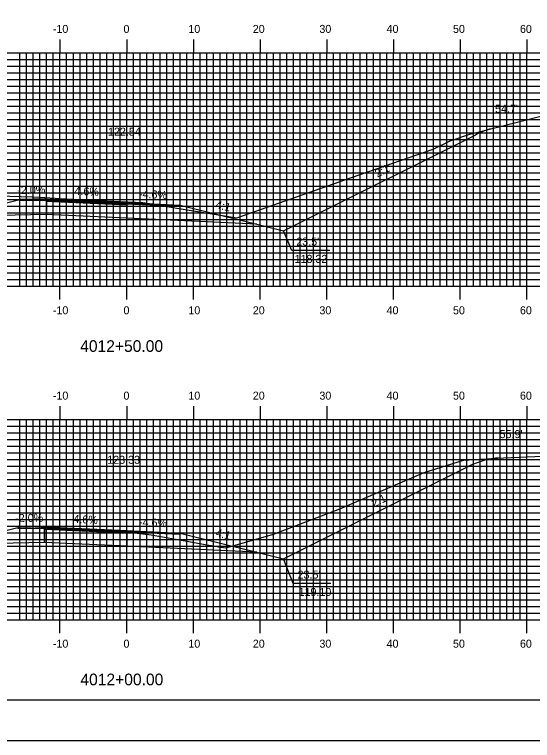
# Model space of a CAD drawing. Extents: x 852934 to 853277, y 364661 to 364881.
# Drawn here: x 853083 to 853160.6, y 364661.3 to 364770.1 of the extents above; entities that cross this region are included whole.
import ezdxf

# ---------------------------------------------------------------- set-up
doc = ezdxf.new("R2010")
doc.units = 0
for name, color, linetype in [('ANNOTATION', 7, 'Continuous'), ('BORDER', 7, 'Continuous'), ('D_Roadway_Centerline_Text', 7, 'Continuous'), ('D_Roadway_Edge_Shoulder', 7, 'Continuous'), ('D_Roadway_Edge_TW', 7, 'Continuous'), ('D_Roadway_Pavement', 7, 'Continuous'), ('D_Roadway_SlopeLines', 7, 'Continuous'), ('D_Roadway_SubGrade', 7, 'Continuous'), ('D_Text_Standard', 7, 'Continuous'), ('H_V ANNOTATION', 7, 'Continuous'), ('M_Roadway_Centerline', 7, 'Continuous'), ('MAJOR', 7, 'Continuous'), ('MINOR', 7, 'Continuous'), ('PLOT BOUNDARY', 7, 'Continuous'), ('S_Roadway_Centerline', 7, 'Continuous')]:
    doc.layers.add(name, color=color, linetype=linetype)

msp = doc.modelspace()

# ---------------------------------------------------------------- linework, layer by layer
at = {"layer": 'ANNOTATION'}
for points in [[(853119.29, 364738.69), (853123.29, 364737.69), (853125.29, 364738.69), (853152.12, 364752.1)], [(853130.22, 364734.75), (853124.53, 364734.75), (853123.29, 364737.69)], [(853119.29, 364689.47), (853123.29, 364688.47), (853125.29, 364689.47), (853151.1, 364702.38)], [(853130.41, 364684.8), (853124.72, 364684.8), (853123.29, 364688.47)]]:
    msp.add_lwpolyline(points, dxfattribs=at)
at = {"layer": 'BORDER'}
msp.add_lwpolyline([(852950.18, 364667.37), (853270.18, 364667.37), (853270.18, 364877.37), (852950.18, 364877.37)], close=True, dxfattribs=at)
at = {"layer": 'D_Roadway_Edge_Shoulder'}
for points in [[(853087.78, 364742.48), (853083.78, 364742.4), (853083.78, 364742.24), (853087.78, 364742.3)], [(853099.78, 364741.93), (853107.78, 364741.56), (853107.78, 364741.4), (853099.78, 364741.75)], [(853087.47, 364693.28), (853083.47, 364693.2), (853083.47, 364693.03), (853087.47, 364693.1)], [(853099.78, 364692.72), (853107.78, 364692.35), (853107.78, 364692.18), (853099.78, 364692.53)]]:
    msp.add_lwpolyline(points, close=True, dxfattribs=at)
at = {"layer": 'D_Roadway_Edge_TW'}
for points in [[(853087.78, 364742.48), (853099.78, 364741.93), (853099.78, 364741.75), (853087.78, 364742.3)], [(853087.47, 364693.28), (853099.78, 364692.72), (853099.78, 364692.53), (853087.47, 364693.1)]]:
    msp.add_lwpolyline(points, close=True, dxfattribs=at)
at = {"layer": 'D_Roadway_Pavement'}
for points in [[(853087.78, 364742.3), (853099.78, 364741.75), (853099.78, 364741.58), (853087.78, 364742.14)], [(853087.47, 364693.1), (853099.78, 364692.53), (853099.78, 364692.37), (853087.47, 364692.93)]]:
    msp.add_lwpolyline(points, close=True, dxfattribs=at)
for points in [[(853087.78, 364742.3), (853087.78, 364742.14)], [(853099.78, 364741.75), (853099.78, 364741.58)], [(853099.78, 364741.75), (853099.78, 364741.58)], [(853087.47, 364693.1), (853087.47, 364692.93)], [(853099.78, 364692.53), (853099.78, 364692.37)], [(853099.78, 364692.53), (853099.78, 364692.37)]]:
    msp.add_lwpolyline(points, dxfattribs=at)
at = {"layer": 'D_Roadway_SlopeLines'}
for centre, start in [((853157.48, 364741.37), 104.298), ((853156.47, 364691.65), 93.6927)]:
    msp.add_arc(centre, 12, start, 116.5651, dxfattribs=at)
at = {"layer": 'D_Roadway_SubGrade'}
for points in [[(853087.78, 364740.14), (853073.57, 364739.85), (853083.78, 364742.4), (853083.78, 364742.24), (853087.78, 364742.3), (853087.78, 364742.14)], [(853087.78, 364742.14), (853099.78, 364741.58), (853099.78, 364739.58), (853087.78, 364740.14)], [(853099.78, 364741.58), (853099.78, 364741.75), (853107.78, 364741.4), (853107.78, 364741.56), (853119.29, 364738.69), (853099.78, 364739.58)], [(853087.47, 364690.93), (853073.26, 364690.65), (853083.47, 364693.2), (853083.47, 364693.03), (853087.47, 364693.1), (853087.47, 364692.93)], [(853087.47, 364692.93), (853099.78, 364692.37), (853099.78, 364690.37), (853087.47, 364690.93)], [(853099.78, 364692.37), (853099.78, 364692.53), (853107.78, 364692.18), (853107.78, 364692.35), (853119.3, 364689.47), (853099.78, 364690.37)]]:
    msp.add_lwpolyline(points, close=True, dxfattribs=at)
at = {"layer": 'MAJOR'}
for p, q in [((853089.78, 364766.37), (853089.78, 364764.37)), ((853099.78, 364766.37), (853099.78, 364764.37)), ((853109.78, 364766.37), (853109.78, 364764.37)), ((853119.78, 364766.37), (853119.78, 364764.37)), ((853129.78, 364766.37), (853129.78, 364764.37)), ((853139.78, 364766.37), (853139.78, 364764.37)), ((853149.78, 364766.37), (853149.78, 364764.37)), ((853159.78, 364766.37), (853159.78, 364764.37)), ((852959.78, 364764.37), (853239.78, 364764.37)), ((852959.78, 364764.37), (853239.78, 364764.37)), ((853089.78, 364729.37), (853089.78, 364764.37)), ((853099.78, 364729.37), (853099.78, 364764.37)), ((853109.78, 364729.37), (853109.78, 364764.37)), ((853119.78, 364729.37), (853119.78, 364764.37)), ((853129.78, 364729.37), (853129.78, 364764.37)), ((853139.78, 364729.37), (853139.78, 364764.37)), ((853149.78, 364729.37), (853149.78, 364764.37)), ((853159.78, 364729.37), (853159.78, 364764.37)), ((852959.78, 364759.37), (853239.78, 364759.37)), ((852959.78, 364754.37), (853239.78, 364754.37)), ((852959.78, 364749.37), (853239.78, 364749.37)), ((852959.78, 364744.37), (853239.78, 364744.37)), ((852959.78, 364739.37), (853239.78, 364739.37)), ((852959.78, 364734.37), (853239.78, 364734.37)), ((852959.78, 364729.37), (853239.78, 364729.37)), ((852959.78, 364729.37), (853239.78, 364729.37)), ((853089.78, 364727.37), (853089.78, 364729.37)), ((853099.78, 364727.37), (853099.78, 364729.37)), ((853109.78, 364727.37), (853109.78, 364729.37)), ((853119.78, 364727.37), (853119.78, 364729.37)), ((853129.78, 364727.37), (853129.78, 364729.37)), ((853139.78, 364727.37), (853139.78, 364729.37)), ((853149.78, 364727.37), (853149.78, 364729.37)), ((853159.78, 364727.37), (853159.78, 364729.37)), ((853089.78, 364711.37), (853089.78, 364709.37)), ((853099.78, 364711.37), (853099.78, 364709.37)), ((853109.78, 364711.37), (853109.78, 364709.37)), ((853119.78, 364711.37), (853119.78, 364709.37)), ((853129.78, 364711.37), (853129.78, 364709.37)), ((853139.78, 364711.37), (853139.78, 364709.37)), ((853149.78, 364711.37), (853149.78, 364709.37)), ((853159.78, 364711.37), (853159.78, 364709.37)), ((852959.78, 364709.37), (853239.78, 364709.37)), ((852959.78, 364709.37), (853239.78, 364709.37)), ((853089.78, 364679.37), (853089.78, 364709.37)), ((853099.78, 364679.37), (853099.78, 364709.37)), ((853109.78, 364679.37), (853109.78, 364709.37)), ((853119.78, 364679.37), (853119.78, 364709.37)), ((853129.78, 364679.37), (853129.78, 364709.37)), ((853139.78, 364679.37), (853139.78, 364709.37)), ((853149.78, 364679.37), (853149.78, 364709.37)), ((853159.78, 364679.37), (853159.78, 364709.37)), ((852959.78, 364704.37), (853239.78, 364704.37)), ((852959.78, 364699.37), (853239.78, 364699.37)), ((852959.78, 364694.37), (853239.78, 364694.37)), ((852959.78, 364689.37), (853239.78, 364689.37)), ((852959.78, 364684.37), (853239.78, 364684.37)), ((852959.78, 364679.37), (853239.78, 364679.37)), ((852959.78, 364679.37), (853239.78, 364679.37)), ((853089.78, 364677.37), (853089.78, 364679.37)), ((853099.78, 364677.37), (853099.78, 364679.37)), ((853109.78, 364677.37), (853109.78, 364679.37)), ((853119.78, 364677.37), (853119.78, 364679.37)), ((853129.78, 364677.37), (853129.78, 364679.37)), ((853139.78, 364677.37), (853139.78, 364679.37)), ((853149.78, 364677.37), (853149.78, 364679.37)), ((853159.78, 364677.37), (853159.78, 364679.37))]:
    msp.add_line(p, q, dxfattribs=at)
at = {"layer": 'MINOR'}
for p, q in [((853083.78, 364729.37), (853083.78, 364764.37)), ((853084.78, 364729.37), (853084.78, 364764.37)), ((853085.78, 364729.37), (853085.78, 364764.37)), ((853086.78, 364729.37), (853086.78, 364764.37)), ((853087.78, 364729.37), (853087.78, 364764.37)), ((853088.78, 364729.37), (853088.78, 364764.37)), ((853090.78, 364729.37), (853090.78, 364764.37)), ((853091.78, 364729.37), (853091.78, 364764.37)), ((853092.78, 364729.37), (853092.78, 364764.37)), ((853093.78, 364729.37), (853093.78, 364764.37)), ((853094.78, 364729.37), (853094.78, 364764.37)), ((853095.78, 364729.37), (853095.78, 364764.37)), ((853096.78, 364729.37), (853096.78, 364764.37)), ((853097.78, 364729.37), (853097.78, 364764.37)), ((853098.78, 364729.37), (853098.78, 364764.37)), ((853100.78, 364729.37), (853100.78, 364764.37)), ((853101.78, 364729.37), (853101.78, 364764.37)), ((853102.78, 364729.37), (853102.78, 364764.37)), ((853103.78, 364729.37), (853103.78, 364764.37)), ((853104.78, 364729.37), (853104.78, 364764.37)), ((853105.78, 364729.37), (853105.78, 364764.37)), ((853106.78, 364729.37), (853106.78, 364764.37)), ((853107.78, 364729.37), (853107.78, 364764.37)), ((853108.78, 364729.37), (853108.78, 364764.37)), ((853110.78, 364729.37), (853110.78, 364764.37)), ((853111.78, 364729.37), (853111.78, 364764.37)), ((853112.78, 364729.37), (853112.78, 364764.37)), ((853113.78, 364729.37), (853113.78, 364764.37)), ((853114.78, 364729.37), (853114.78, 364764.37)), ((853115.78, 364729.37), (853115.78, 364764.37)), ((853116.78, 364729.37), (853116.78, 364764.37)), ((853117.78, 364729.37), (853117.78, 364764.37)), ((853118.78, 364729.37), (853118.78, 364764.37)), ((853120.78, 364729.37), (853120.78, 364764.37)), ((853121.78, 364729.37), (853121.78, 364764.37)), ((853122.78, 364729.37), (853122.78, 364764.37)), ((853123.78, 364729.37), (853123.78, 364764.37)), ((853124.78, 364729.37), (853124.78, 364764.37)), ((853125.78, 364729.37), (853125.78, 364764.37)), ((853126.78, 364729.37), (853126.78, 364764.37)), ((853127.78, 364729.37), (853127.78, 364764.37)), ((853128.78, 364729.37), (853128.78, 364764.37)), ((853130.78, 364729.37), (853130.78, 364764.37)), ((853131.78, 364729.37), (853131.78, 364764.37)), ((853132.78, 364729.37), (853132.78, 364764.37)), ((853133.78, 364729.37), (853133.78, 364764.37)), ((853134.78, 364729.37), (853134.78, 364764.37)), ((853135.78, 364729.37), (853135.78, 364764.37)), ((853136.78, 364729.37), (853136.78, 364764.37)), ((853137.78, 364729.37), (853137.78, 364764.37)), ((853138.78, 364729.37), (853138.78, 364764.37)), ((853140.78, 364729.37), (853140.78, 364764.37)), ((853141.78, 364729.37), (853141.78, 364764.37)), ((853142.78, 364729.37), (853142.78, 364764.37)), ((853143.78, 364729.37), (853143.78, 364764.37)), ((853144.78, 364729.37), (853144.78, 364764.37)), ((853145.78, 364729.37), (853145.78, 364764.37)), ((853146.78, 364729.37), (853146.78, 364764.37)), ((853147.78, 364729.37), (853147.78, 364764.37)), ((853148.78, 364729.37), (853148.78, 364764.37)), ((853150.78, 364729.37), (853150.78, 364764.37)), ((853151.78, 364729.37), (853151.78, 364764.37)), ((853152.78, 364729.37), (853152.78, 364764.37)), ((853153.78, 364729.37), (853153.78, 364764.37)), ((853154.78, 364729.37), (853154.78, 364764.37)), ((853155.78, 364729.37), (853155.78, 364764.37)), ((853156.78, 364729.37), (853156.78, 364764.37)), ((853157.78, 364729.37), (853157.78, 364764.37)), ((853158.78, 364729.37), (853158.78, 364764.37)), ((852959.78, 364763.37), (853239.78, 364763.37)), ((852959.78, 364762.37), (853239.78, 364762.37)), ((852959.78, 364761.37), (853239.78, 364761.37)), ((852959.78, 364760.37), (853239.78, 364760.37)), ((852959.78, 364758.37), (853239.78, 364758.37)), ((852959.78, 364757.37), (853239.78, 364757.37)), ((852959.78, 364756.37), (853239.78, 364756.37)), ((852959.78, 364755.37), (853239.78, 364755.37)), ((852959.78, 364753.37), (853239.78, 364753.37)), ((852959.78, 364752.37), (853239.78, 364752.37)), ((852959.78, 364751.37), (853239.78, 364751.37)), ((852959.78, 364750.37), (853239.78, 364750.37)), ((852959.78, 364748.37), (853239.78, 364748.37)), ((852959.78, 364747.37), (853239.78, 364747.37)), ((852959.78, 364746.37), (853239.78, 364746.37)), ((852959.78, 364745.37), (853239.78, 364745.37)), ((852959.78, 364743.37), (853239.78, 364743.37)), ((852959.78, 364742.37), (853239.78, 364742.37)), ((852959.78, 364741.37), (853239.78, 364741.37)), ((852959.78, 364740.37), (853239.78, 364740.37)), ((852959.78, 364738.37), (853239.78, 364738.37)), ((852959.78, 364737.37), (853239.78, 364737.37)), ((852959.78, 364736.37), (853239.78, 364736.37)), ((852959.78, 364735.37), (853239.78, 364735.37)), ((852959.78, 364733.37), (853239.78, 364733.37)), ((852959.78, 364732.37), (853239.78, 364732.37)), ((852959.78, 364731.37), (853239.78, 364731.37)), ((852959.78, 364730.37), (853239.78, 364730.37)), ((853083.78, 364679.37), (853083.78, 364709.37)), ((853084.78, 364679.37), (853084.78, 364709.37)), ((853085.78, 364679.37), (853085.78, 364709.37)), ((853086.78, 364679.37), (853086.78, 364709.37)), ((853087.78, 364679.37), (853087.78, 364709.37)), ((853088.78, 364679.37), (853088.78, 364709.37)), ((853090.78, 364679.37), (853090.78, 364709.37)), ((853091.78, 364679.37), (853091.78, 364709.37)), ((853092.78, 364679.37), (853092.78, 364709.37)), ((853093.78, 364679.37), (853093.78, 364709.37)), ((853094.78, 364679.37), (853094.78, 364709.37)), ((853095.78, 364679.37), (853095.78, 364709.37)), ((853096.78, 364679.37), (853096.78, 364709.37)), ((853097.78, 364679.37), (853097.78, 364709.37)), ((853098.78, 364679.37), (853098.78, 364709.37)), ((853100.78, 364679.37), (853100.78, 364709.37)), ((853101.78, 364679.37), (853101.78, 364709.37)), ((853102.78, 364679.37), (853102.78, 364709.37)), ((853103.78, 364679.37), (853103.78, 364709.37)), ((853104.78, 364679.37), (853104.78, 364709.37)), ((853105.78, 364679.37), (853105.78, 364709.37)), ((853106.78, 364679.37), (853106.78, 364709.37)), ((853107.78, 364679.37), (853107.78, 364709.37)), ((853108.78, 364679.37), (853108.78, 364709.37)), ((853110.78, 364679.37), (853110.78, 364709.37)), ((853111.78, 364679.37), (853111.78, 364709.37)), ((853112.78, 364679.37), (853112.78, 364709.37)), ((853113.78, 364679.37), (853113.78, 364709.37)), ((853114.78, 364679.37), (853114.78, 364709.37)), ((853115.78, 364679.37), (853115.78, 364709.37)), ((853116.78, 364679.37), (853116.78, 364709.37)), ((853117.78, 364679.37), (853117.78, 364709.37)), ((853118.78, 364679.37), (853118.78, 364709.37)), ((853120.78, 364679.37), (853120.78, 364709.37)), ((853121.78, 364679.37), (853121.78, 364709.37)), ((853122.78, 364679.37), (853122.78, 364709.37)), ((853123.78, 364679.37), (853123.78, 364709.37)), ((853124.78, 364679.37), (853124.78, 364709.37)), ((853125.78, 364679.37), (853125.78, 364709.37)), ((853126.78, 364679.37), (853126.78, 364709.37)), ((853127.78, 364679.37), (853127.78, 364709.37)), ((853128.78, 364679.37), (853128.78, 364709.37)), ((853130.78, 364679.37), (853130.78, 364709.37)), ((853131.78, 364679.37), (853131.78, 364709.37)), ((853132.78, 364679.37), (853132.78, 364709.37)), ((853133.78, 364679.37), (853133.78, 364709.37)), ((853134.78, 364679.37), (853134.78, 364709.37)), ((853135.78, 364679.37), (853135.78, 364709.37)), ((853136.78, 364679.37), (853136.78, 364709.37)), ((853137.78, 364679.37), (853137.78, 364709.37)), ((853138.78, 364679.37), (853138.78, 364709.37)), ((853140.78, 364679.37), (853140.78, 364709.37)), ((853141.78, 364679.37), (853141.78, 364709.37)), ((853142.78, 364679.37), (853142.78, 364709.37)), ((853143.78, 364679.37), (853143.78, 364709.37)), ((853144.78, 364679.37), (853144.78, 364709.37)), ((853145.78, 364679.37), (853145.78, 364709.37)), ((853146.78, 364679.37), (853146.78, 364709.37)), ((853147.78, 364679.37), (853147.78, 364709.37)), ((853148.78, 364679.37), (853148.78, 364709.37)), ((853150.78, 364679.37), (853150.78, 364709.37)), ((853151.78, 364679.37), (853151.78, 364709.37)), ((853152.78, 364679.37), (853152.78, 364709.37)), ((853153.78, 364679.37), (853153.78, 364709.37)), ((853154.78, 364679.37), (853154.78, 364709.37)), ((853155.78, 364679.37), (853155.78, 364709.37)), ((853156.78, 364679.37), (853156.78, 364709.37)), ((853157.78, 364679.37), (853157.78, 364709.37)), ((853158.78, 364679.37), (853158.78, 364709.37)), ((852959.78, 364708.37), (853239.78, 364708.37)), ((852959.78, 364707.37), (853239.78, 364707.37)), ((852959.78, 364706.37), (853239.78, 364706.37)), ((852959.78, 364705.37), (853239.78, 364705.37)), ((852959.78, 364703.37), (853239.78, 364703.37)), ((852959.78, 364702.37), (853239.78, 364702.37)), ((852959.78, 364701.37), (853239.78, 364701.37)), ((852959.78, 364700.37), (853239.78, 364700.37)), ((852959.78, 364698.37), (853239.78, 364698.37)), ((852959.78, 364697.37), (853239.78, 364697.37)), ((852959.78, 364696.37), (853239.78, 364696.37)), ((852959.78, 364695.37), (853239.78, 364695.37)), ((852959.78, 364693.37), (853239.78, 364693.37)), ((852959.78, 364692.37), (853239.78, 364692.37)), ((852959.78, 364691.37), (853239.78, 364691.37)), ((852959.78, 364690.37), (853239.78, 364690.37)), ((852959.78, 364688.37), (853239.78, 364688.37)), ((852959.78, 364687.37), (853239.78, 364687.37)), ((852959.78, 364686.37), (853239.78, 364686.37)), ((852959.78, 364685.37), (853239.78, 364685.37)), ((852959.78, 364683.37), (853239.78, 364683.37)), ((852959.78, 364682.37), (853239.78, 364682.37)), ((852959.78, 364681.37), (853239.78, 364681.37)), ((852959.78, 364680.37), (853239.78, 364680.37))]:
    msp.add_line(p, q, dxfattribs=at)
at = {"layer": 'PLOT BOUNDARY'}
msp.add_lwpolyline([(852933.99, 364661.25), (853273.99, 364661.25), (853273.99, 364881.25), (852933.99, 364881.25)], close=True, dxfattribs=at)
at = {"layer": 'S_Roadway_Centerline'}
for points in [[(853080.57, 364742.96), (853085.62, 364742.77), (853086.76, 364742.73), (853089.81, 364742.54), (853097.74, 364742.13), (853102.21, 364741.92), (853103.53, 364741.73), (853104.77, 364741.56), (853107.02, 364741.14), (853116.31, 364739.63), (853133.5, 364745.67), (853145.72, 364749.95), (853148.29, 364751.17), (853151.22, 364752.16), (853169.96, 364756.93)], [(853081.71, 364693.46), (853083.32, 364693.41), (853083.53, 364693.43), (853090.34, 364693.04), (853096.21, 364692.73), (853098.81, 364692.62), (853103.43, 364692.07), (853109.08, 364691.1), (853111.55, 364690.66), (853113.12, 364690.37), (853113.54, 364690.31), (853114.66, 364690.15), (853121.78, 364692.2), (853131.76, 364695.99), (853144.38, 364701.46), (853150.3, 364703.27), (853156.26, 364703.66), (853169.25, 364704.21)]]:
    msp.add_lwpolyline(points, dxfattribs=at)

# ---------------------------------------------------------------- texts
at = {"layer": 'ANNOTATION'}
for s, rotation, p in [('2:1', 26.5651, (853137.37, 364745.66)), ('-2.0%', 1.1458, (853083.39, 364743.2)), ('4.6%', 357.3663, (853091.93, 364743.1)), ('-4.6%', 357.3663, (853101.61, 364742.65)), ('4:1', 345.9638, (853113.04, 364741.11)), ('2:1', 26.5651, (853136.86, 364696.19)), ('-2.0%', 1.1458, (853083.08, 364693.99)), ('4.6%', 357.3663, (853091.77, 364693.89)), ('-4.6%', 357.3663, (853101.61, 364693.43)), ('4:1', 345.9638, (853113.05, 364691.89))]:
    msp.add_text(s, height=1.2, rotation=rotation, dxfattribs=at).set_placement(p)
for s, p in [("23.5' ", (853125.22, 364735.48)), ('118.32', (853124.96, 364732.88)), ("23.5' ", (853125.41, 364685.53)), ('119.10', (853125.56, 364682.93))]:
    msp.add_text(s, height=1.2, dxfattribs=at).set_placement(p)
at = {"layer": 'D_Roadway_Centerline_Text'}
for s, p in [('122.54', (853096.98, 364751.96)), ('123.33', (853096.87, 364702.75))]:
    msp.add_text(s, height=1.2, dxfattribs=at).set_placement(p)
at = {"layer": 'D_Text_Standard'}
for s, p in [("54.7'", (853155.02, 364755.4)), ("55.9'", (853155.7, 364706.6))]:
    msp.add_text(s, height=1.2, dxfattribs=at).set_placement(p)
at = {"layer": 'H_V ANNOTATION'}
for s, height, p in [('-10', 1.2, (853088.71, 364767.37)), ('0', 1.2, (853099.3, 364767.37)), ('10', 1.2, (853109.03, 364767.37)), ('20', 1.2, (853118.69, 364767.37)), ('30', 1.2, (853128.68, 364767.37)), ('40', 1.2, (853138.75, 364767.37)), ('50', 1.2, (853148.71, 364767.37)), ('60', 1.2, (853158.75, 364767.37)), ('-10', 1.2, (853088.71, 364725.17)), ('0', 1.2, (853099.3, 364725.17)), ('10', 1.2, (853109.03, 364725.17)), ('20', 1.2, (853118.69, 364725.17)), ('30', 1.2, (853128.68, 364725.17)), ('40', 1.2, (853138.75, 364725.17)), ('50', 1.2, (853148.71, 364725.17)), ('60', 1.2, (853158.75, 364725.17)), ('4012+50.00', 1.75, (853092.81, 364719.53)), ('-10', 1.2, (853088.71, 364712.37)), ('0', 1.2, (853099.3, 364712.37)), ('10', 1.2, (853109.03, 364712.37)), ('20', 1.2, (853118.69, 364712.37)), ('30', 1.2, (853128.68, 364712.37)), ('40', 1.2, (853138.75, 364712.37)), ('50', 1.2, (853148.71, 364712.37)), ('60', 1.2, (853158.75, 364712.37)), ('-10', 1.2, (853088.71, 364675.17)), ('0', 1.2, (853099.3, 364675.17)), ('10', 1.2, (853109.03, 364675.17)), ('20', 1.2, (853118.69, 364675.17)), ('30', 1.2, (853128.68, 364675.17)), ('40', 1.2, (853138.75, 364675.17)), ('50', 1.2, (853148.71, 364675.17)), ('60', 1.2, (853158.75, 364675.17)), ('4012+00.00', 1.75, (853092.84, 364669.53))]:
    msp.add_text(s, height=height, dxfattribs=at).set_placement(p)
at = {"layer": 'M_Roadway_Centerline'}
for s, p in [('C', (853086.75, 364742.73)), ('L', (853086.76, 364742.72)), ('C', (853083.52, 364693.43)), ('L', (853083.53, 364693.42))]:
    msp.add_text(s, height=0.0146, dxfattribs=at).set_placement(p)

doc.saveas('drawing.dxf')
